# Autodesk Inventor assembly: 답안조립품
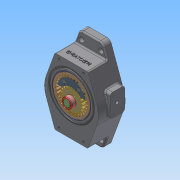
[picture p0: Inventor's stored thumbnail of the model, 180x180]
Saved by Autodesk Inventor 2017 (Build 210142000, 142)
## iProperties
Part Number: 답안조립품
Material: 일반
Document SubType Name: Assembly
Designer: Administrator
Author: Administrator
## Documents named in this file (12)
- C:\Users\Administrator\Desktop\731106V1002\답안조립품.iam
- C:\Users\Administrator\Desktop\731106V1002\본체.ipt
- C:\Users\Administrator\Desktop\731106V1002\오일 실 14 25 4.ipt
- C:\Users\Administrator\Desktop\731106V1002\축.ipt
- C:\Users\Administrator\Desktop\731106V1002\평행 키 5x5x22.ipt
- C:\Users\Administrator\Desktop\731106V1002\오일레스 부시.ipt
- C:\Users\Administrator\Desktop\731106V1002\DU 부시.ipt
- C:\Users\Administrator\Desktop\731106V1002\내접기어.ipt
- C:\Users\Administrator\Desktop\731106V1002\스퍼기어.ipt
- C:\Users\Administrator\Desktop\731106V1002\크레센트.ipt
- C:\Users\Administrator\Desktop\731106V1002\육각 소켓 머리 볼트 M4 x 30.ipt
- C:\Users\Administrator\Desktop\731106V1002\O링 G90.ipt
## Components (2 placed, 2 different names)
1. DU 부시:1
2. O링 G90:1
